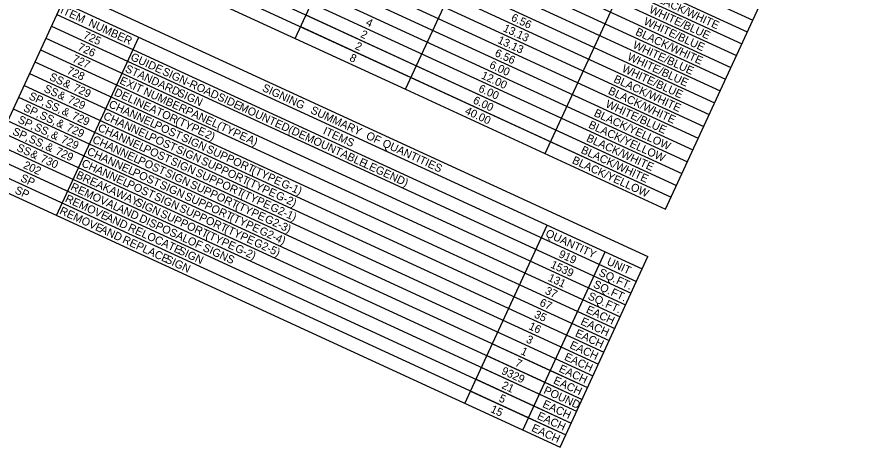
# Model space of a CAD drawing. Extents: x 627405 to 651306, y 367647 to 373430.
# Drawn here: x 650630 to 651257, y 372391 to 372714 of the extents above; entities that cross this region are included whole.
import ezdxf

# ---------------------------------------------------------------- set-up
doc = ezdxf.new("R2010")
doc.units = 0
doc.layers.add('Default', color=7, linetype='Continuous')

msp = doc.modelspace()

# ---------------------------------------------------------------- linework, layer by layer
at = {"layer": 'Default'}
for p, q in [((650839, 372697.82), (650969.78, 372981.62)), ((650675.83, 372944.78), (651181.89, 372711.58)), ((650675.83, 372944.78), (651181.89, 372711.58)), ((650921.79, 372659.67), (651052.57, 372943.47)), ((650667.66, 372927.07), (651173.73, 372693.87)), ((650663.58, 372918.21), (651169.65, 372685.01)), ((650659.5, 372909.36), (651165.57, 372676.16)), ((650655.42, 372900.5), (651161.49, 372667.3)), ((651026.28, 372611.52), (651157.06, 372895.32)), ((650651.34, 372891.65), (651157.41, 372658.45)), ((650647.26, 372882.79), (651153.33, 372649.59)), ((651116.6, 372569.9), (651257.18, 372874.95)), ((650643.18, 372873.94), (651149.25, 372640.74)), ((650639.1, 372865.08), (651145.17, 372631.88)), ((650635.02, 372856.23), (651141.09, 372623.03)), ((650630.94, 372847.37), (651137.01, 372614.17)), ((650626.86, 372838.52), (651132.93, 372605.32)), ((650622.78, 372829.66), (651128.85, 372596.46)), ((650618.7, 372820.81), (651124.77, 372587.61)), ((650614.62, 372811.95), (651120.69, 372578.75)), ((650610.54, 372803.1), (650839, 372697.82)), ((650983, 372792.49), (651177.81, 372702.72)), ((650603.15, 372591.37), (650669.05, 372734.38)), ((650669.05, 372734.38), (651103.39, 372534.24)), ((650664.77, 372725.09), (651099.11, 372524.94)), ((650660.48, 372715.79), (651094.82, 372515.64)), ((650847.16, 372715.53), (650929.95, 372677.38)), ((650656.4, 372706.93), (651090.74, 372506.78)), ((650843.08, 372706.67), (650925.87, 372668.52)), ((650652.32, 372698.08), (651086.66, 372497.93)), ((650660.27, 372565.06), (650721.88, 372698.77)), ((650839, 372697.82), (650921.79, 372659.67)), ((650648.24, 372689.22), (651082.58, 372489.07)), ((650644.16, 372680.37), (651078.5, 372480.22)), ((650929.95, 372677.38), (651124.77, 372587.61)), ((650640.08, 372671.51), (651074.42, 372471.36)), ((650925.87, 372668.52), (651120.69, 372578.75)), ((650636, 372662.66), (651070.34, 372462.51)), ((650921.79, 372659.67), (651116.6, 372569.9)), ((650631.92, 372653.8), (651066.26, 372453.65)), ((650627.84, 372644.95), (651062.18, 372444.8)), ((650623.76, 372636.09), (651058.1, 372435.94)), ((650619.68, 372627.24), (651054.02, 372427.09)), ((650615.6, 372618.38), (651049.94, 372418.23)), ((650611.52, 372609.53), (651045.86, 372409.38)), ((650607.44, 372600.67), (651041.78, 372400.52)), ((650603.15, 372591.37), (651037.49, 372391.23)), ((650966.21, 372424.07), (651027.82, 372557.79)), ((650970.49, 372433.37), (651027.82, 372557.79)), ((651009.6, 372404.08), (651071.21, 372537.79)), ((651013.88, 372413.38), (651071.21, 372537.79)), ((651037.49, 372391.23), (651103.39, 372534.24)), ((650986.82, 372468.79), (651030.21, 372448.8)), ((650982.74, 372459.94), (651026.13, 372439.94)), ((650978.66, 372451.08), (651022.04, 372431.09)), ((651030.21, 372448.8), (651058.1, 372435.94)), ((650974.57, 372442.23), (651017.96, 372422.23)), ((651026.13, 372439.94), (651054.02, 372427.09)), ((650970.49, 372433.37), (651013.88, 372413.38)), ((651022.04, 372431.09), (651049.94, 372418.23)), ((651017.96, 372422.23), (651045.86, 372409.38)), ((651013.88, 372413.38), (651041.78, 372400.52))]:
    msp.add_line(p, q, dxfattribs=at)

# ---------------------------------------------------------------- texts
for s, p in [('BLACK/WHITE', (651105.67, 372727.29)), ('ITEM', (650662.68, 372717.11)), ('WHITE/BLUE', (651103.74, 372717.45)), (' NUMBER', (650681.63, 372708.38)), ('4', (650891.47, 372707.91)), ('6.56', (651000.32, 372711.43)), ('WHITE/BLUE', (651099.66, 372708.6)), ('13.13', (650994.29, 372703.47)), ('BLACK/WHITE', (651093.43, 372700.73)), ('725', (650679.81, 372698.21)), ('2', (650887.46, 372699.02)), ('13.13', (650990.2, 372694.62)), ('726', (650675.65, 372689.39)), ('2', (650883.38, 372690.17)), ('WHITE/BLUE', (651091.49, 372690.88)), ('GUIDE', (650715.19, 372681.91)), ('6.56', (650988.08, 372684.86)), ('WHITE/BLUE', (651087.41, 372682.03)), ('727', (650671.58, 372680.53)), ('8', (650879.27, 372681.33)), ('6.00', (650984.03, 372675.99)), ('728', (650667.5, 372671.68)), ('STANDARD', (650711.11, 372673.05)), (' SIGN-ROADSIDE', (650736.95, 372671.88)), ('WHITE/BLUE', (651083.33, 372673.17)), ('SS', (650654.38, 372666.99)), ('EXIT', (650707.03, 372664.2)), ('12.00', (650977.9, 372668.08)), ('BLACK/WHITE', (651077.11, 372665.31)), ('SS', (650650.3, 372658.13)), (' &', (650662.54, 372663.23)), (' 729', (650670.17, 372659.71)), ('SIGNING', (650813.82, 372658.73)), ('6.00', (650975.87, 372658.28)), ('BLACK/WHITE', (651073.03, 372656.45)), ('SP,', (650638.97, 372652.62)), (' &', (650658.46, 372654.37)), (' 729', (650666.09, 372650.86)), ('DELINEATOR', (650702.95, 372655.34)), (' NUMBER', (650722.75, 372656.95)), (' SIGN', (650748.23, 372655.95)), (' SS,', (650649.11, 372647.95)), ('CHANNEL', (650698.87, 372646.49)), (' MOUNTED', (650794.52, 372645.35)), ('6.00', (650971.78, 372649.43)), ('WHITE/BLUE', (651071.09, 372646.61)), ('SP,', (650634.89, 372643.76)), (' SS,', (650645.03, 372639.09)), (' &', (650661.62, 372642.18)), (' 729', (650669.25, 372638.66)), (' PANEL', (650754.18, 372642.47)), (' SUMMARY', (650848.06, 372642.96)), ('40.00', (650965.66, 372641.52)), ('BLACK/YELLOW', (651062.37, 372639.89)), ('SP,', (650630.81, 372634.91)), (' &', (650657.54, 372633.32)), ('CHANNEL', (650694.79, 372637.63)), (' (TYPE', (650746.91, 372635.09)), ('SP,', (650626.73, 372626.05)), (' SS,', (650640.95, 372630.24)), (' 729', (650665.17, 372629.81)), ('CHANNEL', (650690.7, 372628.78)), (' POST', (650730.84, 372631.75)), (' (TYPE', (650778.06, 372631.46)), (' (DEMOUNTABLE', (650831.29, 372628.41)), ('ITEMS', (650859.39, 372626.46)), ('BLACK/YELLOW', (651058.29, 372631.04)), (' SS,', (650636.87, 372621.38)), (' &', (650653.46, 372624.47)), (' 729', (650661.09, 372620.95)), ('CHANNEL', (650686.62, 372619.92)), (' POST', (650726.76, 372622.9)), (' SIGN', (650751.17, 372622.39)), (' 2)', (650768.91, 372624.95)), (' A)', (650800.06, 372621.33)), (' OF', (650889.6, 372623.82)), ('BLACK/WHITE', (651056.71, 372621.03)), ('SS', (650629.89, 372613.86)), (' &', (650649.38, 372615.61)), (' POST', (650722.68, 372614.04)), (' SUPPORT', (650769.93, 372613.74)), (' QUANTITIES', (650901.78, 372618.2)), (' &', (650638.05, 372610.1)), (' 729', (650657.01, 372612.1)), ('CHANNEL', (650682.54, 372611.07)), (' SIGN', (650747.09, 372613.53)), ('BLACK/WHITE', (651052.63, 372612.18)), ('202', (650634.89, 372600.82)), (' 730', (650645.68, 372606.58)), ('CHANNEL', (650678.46, 372602.21)), (' POST', (650718.6, 372605.19)), (' SIGN', (650743.01, 372604.68)), (' SUPPORT', (650765.85, 372604.89)), (' LEGEND)', (650887.76, 372602.38)), ('BLACK/YELLOW', (651046.05, 372604.47)), (' POST', (650714.52, 372596.33)), (' SIGN', (650738.93, 372595.82)), (' SUPPORT', (650761.77, 372596.03)), (' (TYPE', (650803.96, 372598.06)), ('SP', (650632.69, 372591.1)), ('BREAKAWAY', (650674.38, 372593.36)), (' (TYPE', (650799.88, 372589.21)), ('SP', (650628.51, 372582.02)), ('REMOVAL', (650670.3, 372584.5)), (' POST', (650710.44, 372587.48)), (' SIGN', (650734.85, 372586.97)), (' SUPPORT', (650757.69, 372587.18)), (' G-1)', (650825.96, 372587.92)), ('REMOVE', (650666.22, 372575.65)), (' SIGN', (650730.77, 372578.11)), (' SUPPORT', (650753.61, 372578.32)), (' (TYPE', (650795.8, 372580.35)), (' G-2)', (650821.88, 372579.07)), (' SIGN', (650716.67, 372573.87)), (' (TYPE', (650791.71, 372571.5)), (' G2-1)', (650817.8, 372570.21)), ('REMOVE', (650662.04, 372566.57)), (' AND', (650702.91, 372569.47)), (' SUPPORT', (650735.43, 372565.23)), (' SUPPORT', (650749.53, 372569.47)), (' AND', (650694.59, 372562.58)), (' DISPOSAL', (650719.6, 372561.79)), (' (TYPE', (650787.63, 372562.64)), (' G2-3)', (650813.72, 372561.36)), (' AND', (650690.41, 372553.5)), (' RELOCATE', (650711.28, 372554.89)), (' (TYPE', (650783.55, 372553.79)), (' G2-4)', (650809.63, 372552.5)), (' REPLACE', (650707.1, 372545.81)), (' OF', (650755.81, 372545.1)), (' (TYPE', (650769.46, 372549.55)), ('QUANTITY', (651026.07, 372549.66)), (' SIGNS', (650767.26, 372539.82)), (' G-2)', (650791.46, 372539.41)), (' G2-5)', (650805.55, 372543.65)), (' SIGN', (650748.84, 372537.58)), ('919', (651035.96, 372534.09)), (' SIGN', (650739.11, 372531.06)), ('1539', (651029.84, 372526.18)), ('UNIT', (651072, 372528.49)), ('SQ.', (651065.96, 372520.27)), ('131', (651027.95, 372516.32)), (' FT.', (651077.01, 372515.18)), ('37', (651025.74, 372506.6)), ('SQ.', (651061.88, 372511.41)), ('SQ.', (651057.8, 372502.56)), (' FT.', (651072.93, 372506.32)), ('67', (651021.66, 372497.74)), (' FT.', (651068.85, 372497.47)), ('35', (651017.64, 372488.86)), ('EACH', (651056.49, 372492.43)), ('EACH', (651052.41, 372483.57)), ('16', (651013.49, 372480.04)), ('EACH', (651048.32, 372474.72)), ('3', (651011.54, 372470.2)), ('EACH', (651044.24, 372465.86)), ('1', (651007.55, 372461.3)), ('EACH', (651040.16, 372457.01)), ('7', (651003.31, 372452.52)), ('9329', (650993.11, 372446.49)), ('EACH', (651036.08, 372448.15)), ('EACH', (651032, 372439.3)), ('21', (650993.27, 372435.68)), ('POUND', (651024.67, 372431.94)), ('5', (650991.12, 372425.93)), ('EACH', (651023.84, 372421.59)), ('15', (650984.9, 372417.8)), ('EACH', (651019.76, 372412.73)), ('EACH', (651015.58, 372403.66))]:
    msp.add_text(s, height=6, rotation=335.25934, dxfattribs=at).set_placement(p)

doc.saveas('drawing.dxf')
